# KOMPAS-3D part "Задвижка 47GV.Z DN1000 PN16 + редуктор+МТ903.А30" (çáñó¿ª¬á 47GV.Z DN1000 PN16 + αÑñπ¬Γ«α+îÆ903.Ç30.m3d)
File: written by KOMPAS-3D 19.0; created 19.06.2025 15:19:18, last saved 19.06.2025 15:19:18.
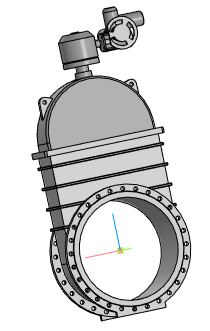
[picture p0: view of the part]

Document properties: Полное имя файла: Задвижка 47GV.Z DN1000 PN16 + редуктор+МТ903.А30.a3d

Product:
- Part/product: Задвижка 47GV.Z DN1000 PN16 + редуктор+МТ903.А30
    Масса: 4737.67

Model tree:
1. Операция без истории:1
